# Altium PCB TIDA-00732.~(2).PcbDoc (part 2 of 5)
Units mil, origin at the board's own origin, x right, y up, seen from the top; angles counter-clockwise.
Board outline 8994.78 x 4186 mil, 6 copper layers (Top Layer, GND1, PWR1, PWR2, GND2, Bottom Layer), stack 97.668 mil thick; 693 components, 463 nets, 2087 pads, 616 vias.
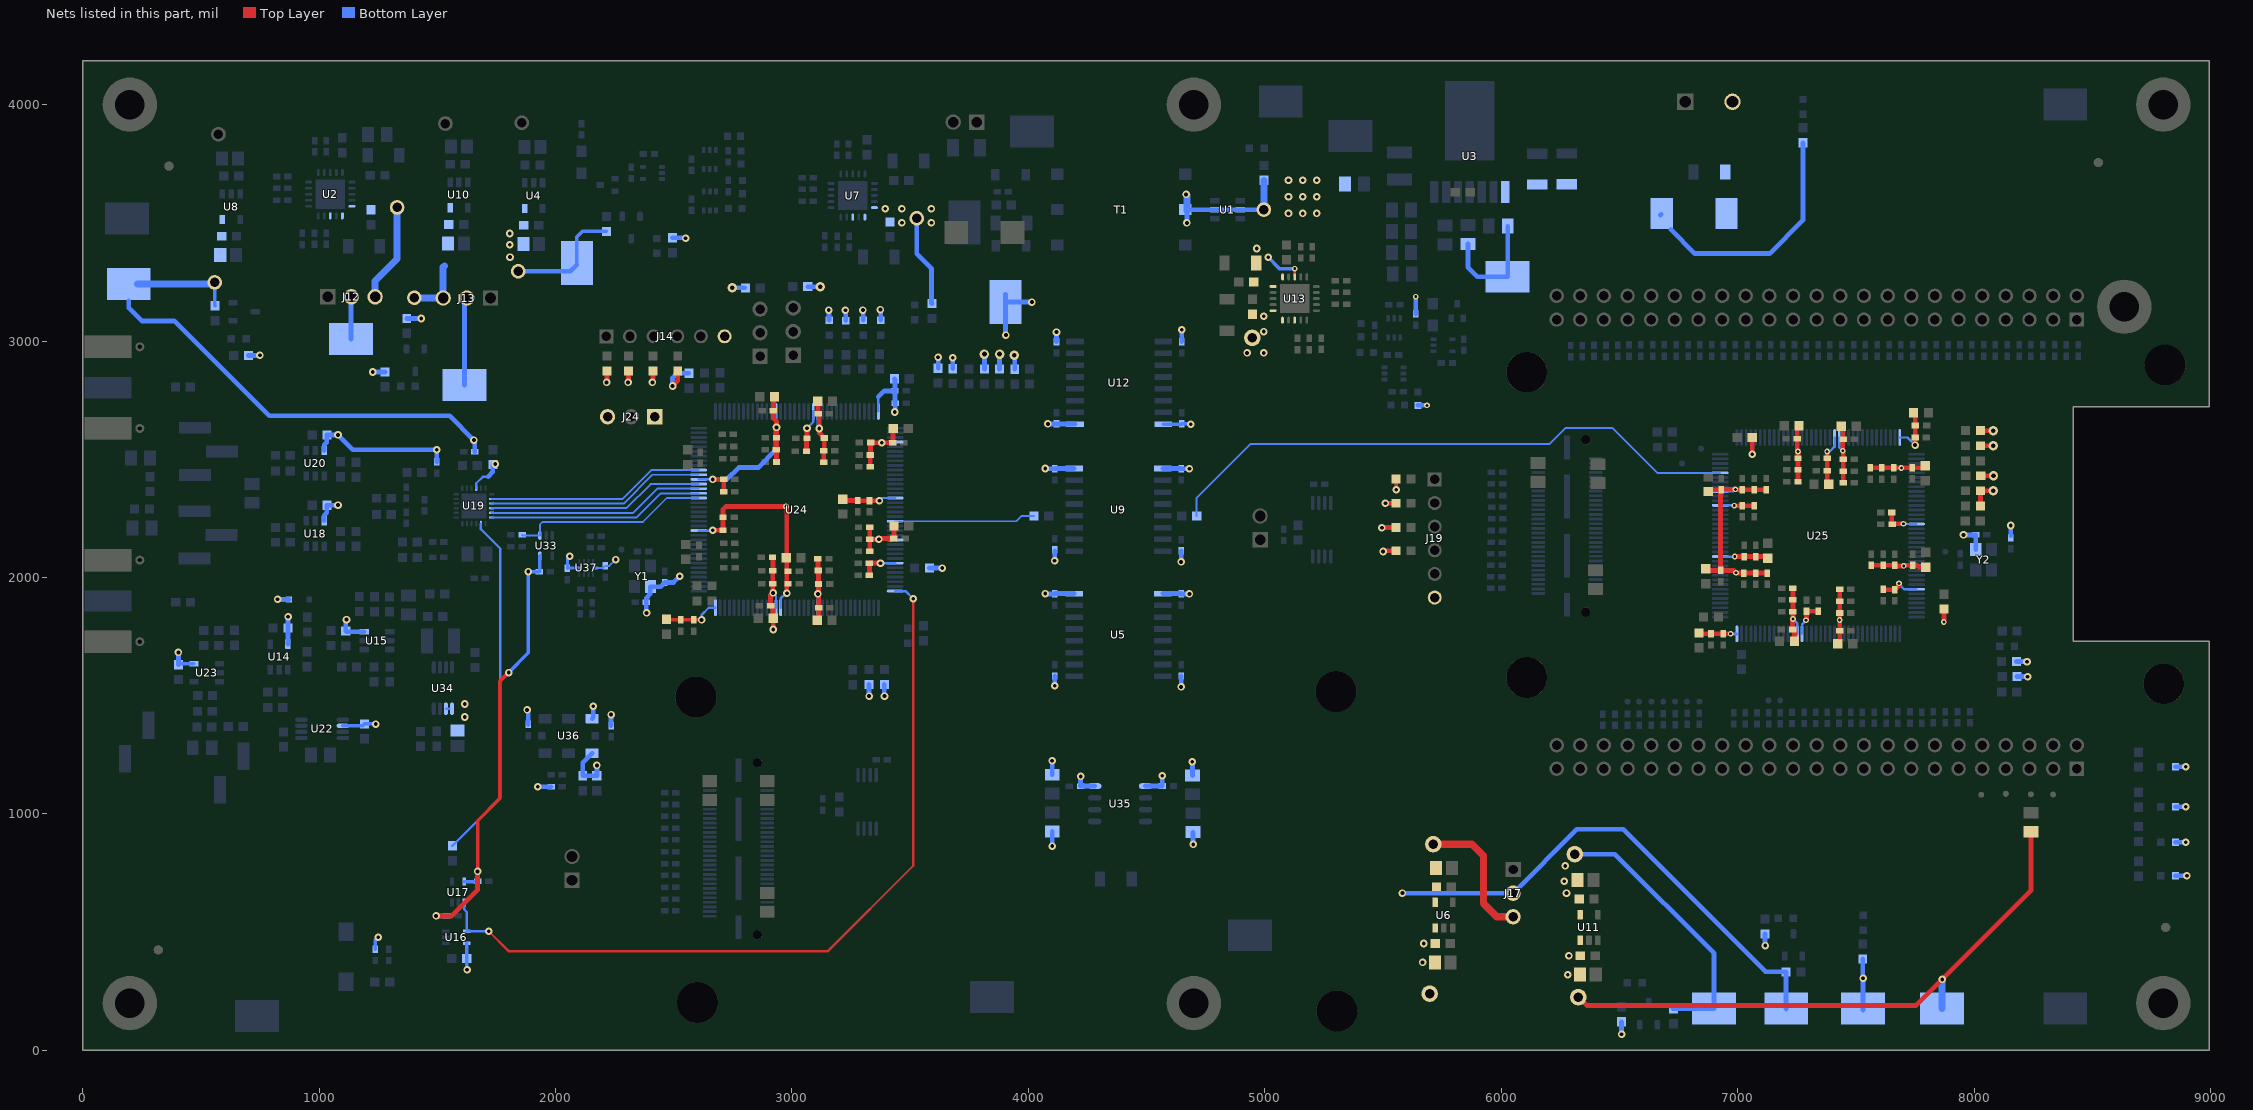
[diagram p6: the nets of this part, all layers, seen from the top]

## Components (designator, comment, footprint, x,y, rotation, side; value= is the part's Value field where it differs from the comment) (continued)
U23 "OPA376AIDBVR" DBV0005A_N 525,1597.02 r180 bottom
U24 "XC3S50AN-5TQG144C" TQ144_N 3021,2287 r270 bottom
U25 "XC3S50AN-5TQG144C" TQ144_N 7341,2177 r270 bottom
U26 "TLV3012AIDCKR" DCK0006A_L 2652,3768 r270 bottom
U27 "SN74LVC1G08DCKR" DCK0005A_L 2410,3711 r180 bottom
U28 "BR24G32FVT-3AGE2" TSOP65P640X120-8N 5240.5,2202 r270 bottom
U29 "TLV3012AIDCKR" DCK0006A_L 2653,3593 r270 bottom
U30 "TLV3012AIDCKR" DCK0006A_L 5546,2863 r180 bottom
U31 "SN74LVC1G08DCKR" DCK0005A_L 5754,2982 r0 bottom
U32 "TLV3012AIDCKR" DCK0006A_L 5547,3056 r90 bottom
U33 "SN74AUP1G80DCK" DCK-5 1960,2135 r0 bottom
U34 "REF6041AIDGK" DGK0008A_N 1523.8,1532.4 r90 bottom
U35 "ISO1541DR" D0008A_N 4388,1043 r180 bottom
U36 "LMK61E2-SIAR" SIA0008B 2055,1330 r90 bottom
U37 "SN65LVDS4RSET" RSE0010A 2129.65,2040.51 r90 bottom
Y1 "ASTMLPE-125.000MHZ-LJ-E-T" TXC_AU 2367.65,2004.51 r0 bottom
Y2 "ASTMLPE-125.000MHZ-LJ-E-T" TXC_AU 8040,2075 r180 bottom
ZZ1 "This Assembly Note is for PCB labels only" AssemblyNoteLabel 400,4620 r0 top
ZZ2 "These assemblies are ESD sensitive, ESD precautions shall be observed." AssemblyNote 397.78,4554.11 r0 top
ZZ3 "These assemblies must be clean and free from flux and all contaminants. Use of no clean flux is not acceptable." AssemblyNote 397.78,4465.56 r0 top
ZZ4 "These assemblies must comply with workmanship standards IPC-A-610 Class 2, unless otherwise specified." AssemblyNote 397.78,4377 r0 top

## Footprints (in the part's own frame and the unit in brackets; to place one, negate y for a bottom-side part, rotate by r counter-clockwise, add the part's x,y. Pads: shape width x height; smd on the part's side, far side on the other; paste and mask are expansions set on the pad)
0402 [mm] "0402 from SM-752 data"
  rect 0.8x0.6 smd: 1(-0.6,0) 2(0.6,0)
  silkscreen extent -1.22,-0.52 1.22,0.52, body extent -0.55,-0.3 0.55,0.3, height 0.6
0603#1 [mm] "0603 from SM-752 data"
  rect 1x0.95 smd: 1(-0.8,0) 2(0.8,0)
  silkscreen extent -1.52,-0.69 1.52,0.69, body extent -0.87,-0.47 0.87,0.47, height 1
0603#2 [mm] "0603 from SM-752 data"
  rect 1x0.95 smd: 1(0.8,0) 2(-0.8,0)
  silkscreen extent -1.52,-0.69 1.52,0.69, body extent -0.87,-0.47 0.87,0.47, height 1
0603_120 [mm] "0603_120"
  rect 1x1 smd: 1(-0.8,0) 2(0.8,0)
  silkscreen extent -0.1,-0.58 0.1,0.58, body extent -0.87,-0.48 0.87,0.48, height 1.2
0603_HV [mil] "Ernesto recommended land pattern.  26 mil between pads."
  rect 30x30 smd: 1(-28,0) 2(28,0)
  silkscreen extent -52,-24 52,24, body extent -34,-19 34,19, height 39
0805 [mm] "0805 from SM-752 data"
  rect 1.3x1.5 smd: 1(-0.85,0) 2(0.85,0)
  silkscreen extent -1.72,-0.97 1.72,0.97, body extent -1.1,-0.72 1.1,0.72, height 1.45
0805_HV [mil] "0805 with 30mil clearance between pads"
  rect 50x63 smd: 1(-40,0) 2(40,0)
  silkscreen extent -74,-40 74,40, body extent -43,-29 43,29, height 57
1206 [mm] "1206 from SM-752 data"
  rect 1.3x1.85 smd: 1(-1.45,0) 2(1.45,0)
  silkscreen extent -2.4,-1.21 2.4,1.21, body extent -1.7,-0.9 1.7,0.9, height 1.35
1206_190 [mm] "1206_190"
  rect 1.1x1.6 smd: 1(-1.7,0) 2(1.7,0)
  silkscreen extent -0.9,-1 0.9,1, body extent -1.75,-0.95 1.75,0.95, height 1.9
1210 [mm] "1210 from SM-752 data"
  rect 1.3x2.7 smd: 1(-1.45,0) 2(1.45,0)
  silkscreen extent -2.32,-1.57 2.32,1.57, body extent -1.7,-1.35 1.7,1.35, height 1.35
1210_280 [mm] "SMD, 2-Leads, Body 3.6x2.8mm, Height 2.8mm"
  rect 1.1x2.2 smd: 1(-1.65,0) 2(1.65,0)
  silkscreen extent -0.84,-1.4 0.84,1.4, body extent -1.8,-1.4 1.8,1.4, height 2.8
7343-43 [mm] "Medium density IPC based on Kemet T495 series"
  rect 2.55x2.45 smd: 1(-3.025,0) 2(3.025,0)
  silkscreen extent -4.56,-2.3 3.8,2.3, body extent -3.8,-2.3 3.8,2.3, height 4.3
APT2012_Green [mm] "SMD, 2-Leads, Body 2x1.25mm"
  rect 1.25x1.1 smd: 1(-1.175,0) 2(1.175,0)
  silkscreen extent -1.5,-1 2.4,1, body extent -1,-0.62 1,0.63, height 0.76
AssemblyNote [mil] "Assembly Note"
AssemblyNoteLabel [mil] "Assembly Note for PCB Labels"
B_F_PMSSS4400025PH [mil] "MACHINE SCREW PAN PHILLIPS 4-40"
  round 230 hole 125: 1(0,0)
  body extent -110,-109 109,110, height 79
CONN_ED120-2DS [mm] "ONSHORE"
  rect 1.75x1.75 hole 1.25: 1(0,-2.54)
  round 1.75 hole 1.25: 2(0,2.54)
  silkscreen extent -5,-5.6 4,5.12, body extent -5,-5.6 4.15,5.12, height 13.1
D0008A_N [mm] "SOIC, 8-Leads, Body 4.9x3.9mm, Pitch 1.27mm, IPC Medium Density"
  oval 1.45x0.6 smd: 1(-2.725,1.905) 2(-2.725,0.635) 3(-2.725,-0.635) 4(-2.725,-1.905) 5(2.725,-1.905) 6(2.725,-0.635) 7(2.725,0.635) 8(2.725,1.905)
  silkscreen extent -3.3,-2.5 0.9,2.5, body extent -3,-2.45 3,2.45, height 1.63
DBV0005A_N [mm] "SOT23, 5-Leads, Body 2.9x1.6mm, Pitch 0.95mm, Lead Span 2.8mm, IPC Medium Density"
  rrect17% 1x0.6 smd: 1(-1.375,0.95) 2(-1.375,0) 3(-1.375,-0.95) 4(1.375,-0.95) 5(1.375,0.95)
  silkscreen extent -1.63,-1.55 0.38,1.55, body extent -1.42,-1.46 1.42,1.46, height 1.09
DBV0006A_N [mm] "SOT23, 6-Leads, Body 2.9x1.6mm, Pitch 0.95mm, Lead Span 2.8mm, IPC Medium Density"
  rrect17% 1x0.6 smd: 1(-1.375,0.95) 2(-1.375,0) 3(-1.375,-0.95) 4(1.375,-0.95) 5(1.375,0) 6(1.375,0.95)
  silkscreen extent -1.68,-1.55 0.5,1.55, body extent -1.42,-1.46 1.42,1.46, height 1.12
DCK0005A_L [mm] "SOT353, 5-Leads, Body 2x1.3mm, Pitch 0.65mm, Lead Span 2.1mm, IPC High Density"
  rrect25% 0.65x0.4 smd: 1(-1.025,0.65) 2(-1.025,0) 3(-1.025,-0.65) 4(1.025,-0.65) 5(1.025,0.65)
  silkscreen extent -1.27,-1.09 0.56,1.09, body extent -1.14,-1 1.14,1, height 0.95
DCK0005A_N [mm] "SOT353, 5-Leads, Body 2x1.3mm, Pitch 0.65mm, Lead Span 2.1mm, IPC Medium Density"
  rrect25% 0.85x0.4 smd: 1(-1.125,0.65) 2(-1.125,0) 3(-1.125,-0.65) 4(1.125,-0.65) 5(1.125,0.65)
  silkscreen extent -1.48,-1.02 0.55,1.1, body extent -1.14,-1 1.14,1, height 0.95
DCK0006A_L [mm] "SOT23, 6-Leads, Body 2x1.3mm, Pitch 0.65mm, Lead Span 2.1mm, IPC High Density"
  rrect25% 0.65x0.4 smd: 1(-1.025,0.65) 2(-1.025,0) 3(-1.025,-0.65) 4(1.025,-0.65) 5(1.025,0) 6(1.025,0.65)
  silkscreen extent -1.3,-1.07 0.55,1.1, body extent -1.14,-1 1.14,1, height 0.95
DCK-5 [mil]
  oval 15x38 smd: 1(-25.9,-43.4) 2(0.1,-43.4) 3(26.1,-43.4) 4(26.1,43.6) 5(-25.9,43.6)
DGK0008A_N [mm] "TSOP, 8-Leads, Body 3x3mm, Pitch 0.65mm, IPC Medium Density"
  oval 1.35x0.45 smd: 1(-2.225,0.975) 2(-2.225,0.325) 3(-2.225,-0.325) 4(-2.225,-0.975) 5(2.225,-0.975) 6(2.225,-0.325) 7(2.225,0.325) 8(2.225,0.975)
  silkscreen extent -2.75,-1.55 0.95,1.55, body extent -2.45,-1.5 2.45,1.5, height 0.96
DW0016B_N [mm] "SOIC, 16-Leads, Body 10.5x7.6mm, Pitch 1.27mm, IPC Medium Density"
  rrect17% 1.9x0.6 smd: 1(-4.75,4.445) 2(-4.75,3.175) 3(-4.75,1.905) 4(-4.75,0.635) 5(-4.75,-0.635) 6(-4.75,-1.905) 7(-4.75,-3.175) 8(-4.75,-4.445) 9(4.75,-4.445) 10(4.75,-3.175) 11(4.75,-1.905) 12(4.75,-0.635) 13(4.75,0.635) 14(4.75,1.905) 15(4.75,3.175) 16(4.75,4.445)
  silkscreen extent -5.6,-5.25 3.4,5.25, body extent -5.17,-5.15 5.17,5.15, height 2.59
Fiducial10-20 [mm]
  round 1 smd mask+0.5: 1(0,0)
  Top Layer keep-out circle w1.178: c0,0 r0.5
JOHNSON_142-0701-801 [mil] "Johnson Components recommended land pattern"
  rect 90x200 smd: 1(0,0)
  round 38 hole 18: 2(-172.5,-135) 3(172.5,-135)
  rect 95x200 smd: 2(-172.5,0) 3(172.5,0)
  rect 95x200 smd far side: 4(-172.5,0) 5(172.5,0)
  Top Layer lines w18: 172.5,0 172.5,-135 ; -172.5,0 -172.5,-135
  Bottom Layer lines w18: 172.5,0 172.5,-135 ; -172.5,0 -172.5,-135
  silkscreen extent -235,-170 235,100, body extent -190,-92 190,480, height 165
Keystone_1902C [mil] "Hex Standoff, 4-40 threaded, nylon"
  round 1 on Mech3: 0(0,0)
  body extent -145,-126 146,126, height 501
Label_650x200 [mil] "Thermal Transfer Label"
  round 1 on Mech14: 0(0,0)
  silkscreen extent -325,-100 325,100, body extent -326,-101 326,101, height 1
Molex_87898-0204 [mm] "Header, 2.54 mm, 2x1, R/A, SMT"
  rect 1.27x2.96 smd: 1(-1.27,1.8) 2(1.27,-1.8)
  silkscreen extent -2.54,-1.27 2.54,1.27, body extent -2.54,-2.4 2.54,2.4, height 9.65
RGE0024H [mm] "QFN, 24-Leads, Body 4x4mm, Pitch 0.5mm, Thermal Pad 2.7x2.7mm, TI Recommended"
  oval 0.6x0.24 smd: 1(-1.9,1.25) 2(-1.9,0.75) 3(-1.9,0.25) 4(-1.9,-0.25) 5(-1.9,-0.75) 6(-1.9,-1.25) 13(1.9,-1.25) 14(1.9,-0.75) 15(1.9,-0.25) 16(1.9,0.25) 17(1.9,0.75) 18(1.9,1.25)
  oval 0.24x0.6 smd: 7(-1.25,-1.9) 8(-0.75,-1.9) 9(-0.25,-1.9) 10(0.25,-1.9) 11(0.75,-1.9) 12(1.25,-1.9) 19(1.25,1.9) 20(0.75,1.9) 21(0.25,1.9) 22(-0.25,1.9) 23(-0.75,1.9) 24(-1.25,1.9)
  rect 2.7x2.7 smd paste-1.35: 25(0,0)
  silkscreen extent -2.22,-2.22 2.22,2.22, body extent -2.07,-2.07 2.07,2.07, height 1.01
RGW0020A [mm] "QFN, 20-Leads, Body 5x5mm, Pitch 0.65mm, Thermal Pad 3.15x3.15mm, TI Recommended"
  oval 0.75x0.3 smd: 1(-2.325,1.3) 2(-2.325,0.65) 3(-2.325,0) 4(-2.325,-0.65) 5(-2.325,-1.3) 11(2.325,-1.3) 12(2.325,-0.65) 13(2.325,0) 14(2.325,0.65) 15(2.325,1.3)
  oval 0.3x0.75 smd: 6(-1.3,-2.325) 7(-0.65,-2.325) 8(0,-2.325) 9(0.65,-2.325) 10(1.3,-2.325) 16(1.3,2.325) 17(0.65,2.325) 18(0,2.325) 19(-0.65,2.325) 20(-1.3,2.325)
  rect 3.15x3.15 smd paste-1.575: 21(0,0)
  silkscreen extent -2.73,-2.73 2.73,2.73, body extent -2.58,-2.57 2.57,2.58, height 1.01
RSE0010A [mm] "QFN, 10-Leads, Body 1.5x2mm, Pitch 0.5mm, TI Recommended"
  rect 0.55x0.2 smd: 1(-0.675,0.75) 2(-0.675,0.25) 3(-0.675,-0.25) 4(-0.675,-0.75) 6(0.675,-0.75) 7(0.675,-0.25) 8(0.675,0.25) 9(0.675,0.75)
  rect 0.3x0.6 smd: 5(0,-0.9) 10(0,0.9)
  silkscreen extent -1.07,-1.17 0.77,1.18, body extent -0.77,-1.02 0.78,1.03, height 0.61
Samtec_HTSW-103-07-G-S [mm] "Samtec 100mil, 1x3, 230 mil above insulator"
  rect 1.65x1.65 hole 1.016 mask+0: 1(-2.54,0)
  round 1.65 hole 1.016 mask+0: 2(0,0) 3(2.54,0)
  silkscreen extent -4.57,-1.27 3.81,1.27, body extent -3.81,-1.27 3.81,1.27, height 8.38
Samtec_QTH-030-01-x-D-A [mil] "Header (Shrouded), 19.7mil, 30x2, SMT"
  rect 12x57 smd: 1(-285.7,121.5) 2(-285.7,-121.5) 3(-266,121.5) 4(-266,-121.5) 5(-246.3,121.5) 6(-246.3,-121.5) 7(-226.6,121.5) 8(-226.6,-121.5) 9(-206.9,121.5) 10(-206.9,-121.5) 11(-187.2,121.5) 12(-187.2,-121.5) 13(-167.5,121.5) 14(-167.5,-121.5) 15(-147.8,121.5) 16(-147.8,-121.5) 17(-128.1,121.5) 18(-128.1,-121.5) 19(-108.4,121.5) 20(-108.4,-121.5) 21(-88.7,121.5) 22(-88.7,-121.5) 23(-69,121.5) 24(-69,-121.5) 25(-49.3,121.5) 26(-49.3,-121.5) 27(-29.6,121.5) 28(-29.6,-121.5) 29(-9.9,121.5) 30(-9.9,-121.5) 31(9.8,121.5) 32(9.8,-121.5) 33(29.5,121.5) 34(29.5,-121.5) 35(49.2,121.5) 36(49.2,-121.5) 37(68.9,121.5) 38(68.9,-121.5) 39(88.6,121.5) 40(88.6,-121.5) 41(108.3,121.5) 42(108.3,-121.5) 43(128,121.5) 44(128,-121.5) 45(147.7,121.5) 46(147.7,-121.5) 47(167.4,121.5) 48(167.4,-121.5) 49(187.1,121.5) 50(187.1,-121.5) 51(206.8,121.5) 52(206.8,-121.5) 53(226.5,121.5) 54(226.5,-121.5) 55(246.2,121.5) 56(246.2,-121.5) 57(265.9,121.5) 58(265.9,-121.5) 59(285.6,121.5) 60(285.6,-121.5)
  round 40 hole 40 unplated mask+10: MH1(-364,80) MH2(364,80)
  rect 100x25 smd: MP1(-332.7,0) MP4(332.3,0)
  rect 185x25 smd: MP2(-125.2,0) MP3(124.8,0)
  silkscreen extent -394,-118 394,131, body extent -394,-140 394,140, height 170
Samtec_TSM-103-01-X-SV [mil] "Samtec recommended land pattern"
  rect 50x135 smd: 1(-100,57.5) 2(0,-57.5) 3(100,57.5)
  silkscreen extent -150,-50 150,50, body extent -150,-104 150,104, height 381
Samtec_TSW-123-07-x-D#1 [mm] "Header, 2.54 mm, 23x2, TH"
  rect 1.55x1.55 hole 1.02: 1(-1.27,-27.94)
  round 1.55 hole 1.02: 2(1.27,-27.94) 3(-1.27,-25.4) 4(1.27,-25.4) 5(-1.27,-22.86) 6(1.27,-22.86) 7(-1.27,-20.32) 8(1.27,-20.32) 9(-1.27,-17.78) 10(1.27,-17.78) 11(-1.27,-15.24) 12(1.27,-15.24) 13(-1.27,-12.7) 14(1.27,-12.7) 15(-1.27,-10.16) 16(1.27,-10.16) 17(-1.27,-7.62) 18(1.27,-7.62) 19(-1.27,-5.08) 20(1.27,-5.08) 21(-1.27,-2.54) 22(1.27,-2.54) 23(-1.27,0) 24(1.27,0) 25(-1.27,2.54) 26(1.27,2.54) 27(-1.27,5.08) 28(1.27,5.08) 29(-1.27,7.62) 30(1.27,7.62) 31(-1.27,10.16) 32(1.27,10.16) 33(-1.27,12.7) 34(1.27,12.7) 35(-1.27,15.24) 36(1.27,15.24) 37(-1.27,17.78) 38(1.27,17.78) 39(-1.27,20.32) 40(1.27,20.32) 41(-1.27,22.86) 42(1.27,22.86) 43(-1.27,25.4) 44(1.27,25.4) 45(-1.27,27.94) 46(1.27,27.94)
  silkscreen extent -2.54,-29.76 2.54,29.21, body extent -2.54,-29.21 2.54,29.21, height 2.54
Samtec_TSW-123-07-x-D#2 [mm] "Header, 2.54 mm, 23x2, TH"
  rect 1.55x1.55 hole 1.02: 1(-1.27,0.254)
  round 1.55 hole 1.02: 2(1.27,0.254) 3(-1.27,2.794) 4(1.27,2.794) 5(-1.27,5.334) 6(1.27,5.334) 7(-1.27,7.874) 8(1.27,7.874) 9(-1.27,10.414) 10(1.27,10.414) 11(-1.27,12.954) 12(1.27,12.954) 13(-1.27,15.494) 14(1.27,15.494) 15(-1.27,18.034) 16(1.27,18.034) 17(-1.27,20.574) 18(1.27,20.574) 19(-1.27,23.114) 20(1.27,23.114) 21(-1.27,25.654) 22(1.27,25.654) 23(-1.27,28.194) 24(1.27,28.194) 25(-1.27,30.734) 26(1.27,30.734) 27(-1.27,33.274) 28(1.27,33.274) 29(-1.27,35.814) 30(1.27,35.814) 31(-1.27,38.354) 32(1.27,38.354) 33(-1.27,40.894) 34(1.27,40.894) 35(-1.27,43.434) 36(1.27,43.434) 37(-1.27,45.974) 38(1.27,45.974) 39(-1.27,48.514) 40(1.27,48.514) 41(-1.27,51.054) 42(1.27,51.054) 43(-1.27,53.594) 44(1.27,53.594) 45(-1.27,56.134) 46(1.27,56.134)
  silkscreen extent -2.54,-1.57 2.54,57.4, body extent -2.54,-1.02 2.54,57.4, height 2.54
SIA0008B [mm] "SIP 8-Leads, Body 5x7mm"
  rrect17% 1x0.6 on Bottom Paste: 1(-1.85,2.14) 1(-1.85,2.94) 2(-1.85,-0.4) 2(-1.85,0.4) 3(-1.85,-2.94) 3(-1.85,-2.14) 4(1.85,-2.94) 4(1.85,-2.14) 5(1.85,-0.4) 5(1.85,0.4) 6(1.85,2.14) 6(1.85,2.94)
  rrect10% 1x1.4 smd paste-0.5: 1(-1.85,2.54) 2(-1.85,0) 3(-1.85,-2.54) 4(1.85,-2.54) 5(1.85,0) 6(1.85,2.54)
  rrect12% 0.8x0.8 smd: 7(0,2.865) 8(0,-2.865)
  silkscreen extent -2.64,-3.63 2.64,3.63, body extent -2.56,-3.56 2.56,3.56, height 1.13
SMC [mm] "DO-214-AB/SMC; 2 C-Bend Leads; Body 7.9 x 5.9 mm, inc. leads (LxW)"
  rect 2.4x3.3 smd: 1(3.475,0) 2(-3.475,0)
  silkscreen extent -5.43,-2.05 5.07,2.05
SOD-123 [mm] "On Semi recommended land pattern"
  rect 0.915x1.22 smd: 1(-1.637,0) 2(1.637,0)
  silkscreen extent -2.74,-1.17 2.03,1.17, body extent -1.93,-0.9 1.93,0.9, height 1.35
sod-323 [mm] "NXP recommended land pattern"
  rect 0.6x0.6 smd paste-0.05: 1(-1.1,0) 2(1.1,0)
  silkscreen extent -2.06,-0.86 1.53,0.86, body extent -1.3,-0.67 1.3,0.68, height 1.1
SOT-23 [mm] "SOT23, 3-Leads, Body 2.9x1.3mm, Pitch 0.95mm, Lead Span 2.5mm, IPC Medium Density"
  rrect50% 1x0.6 smd: 1(-1.2,0.95) 2(-1.2,-0.95) 3(1.2,0)
  silkscreen extent -1.62,-1.5 0.7,1.5, body extent -1.16,-1.45 1.21,1.45, height 1
SOT-323 [mm] "Zetex recommended land pattern.  March 2007"
  rect 0.8x0.6 smd: 1(-0.8,0.65) 2(-0.8,-0.65) 3(0.8,0)
  silkscreen extent -1.14,-1.22 0.77,1.22, body extent -1.13,-1.13 1.12,1.12, height 1.13
Sullins_PEC06SAAN [mm] "TH, 6-Leads, Body 608x100mil, Pitch 100mil"
  rect 1.5x1.5 hole 1.016: 1(-6.35,0)
  round 1.5 hole 1.016: 2(-3.81,0) 3(-1.27,0) 4(1.27,0) 5(3.81,0) 6(6.35,0)
  silkscreen extent -8.64,-1.27 7.72,1.27, body extent -7.72,-1.27 7.72,1.27, height 8.59
SW_EVQPNF04M [mm] "SMD, 2-Leads, Body 6x4mm"
  rect 2x1.6 smd: 1(-2.7,0) 2(2.7,0)
  silkscreen extent -4.37,-1.75 3,1.75, body extent -3.6,-1.75 3.6,1.75, height 4.3
Testpoint_Keystone_Compact [mil] "Compact SMT test point"
  rect 185x135 smd: 1(0,0)
  silkscreen extent -110,-80 110,80, body extent -75,-56 75,56, height 91
TI_Stacked_Overlay_Small [mil]
  silkscreen extent -418,-98 418,98
TP-040_RND [mil]
  round 70 / inner round 62 / far side round 62 hole 40: 1(0,0)
TP_25MIL-SMT [mil]
  round 25 smd mask-2.5: 1(0,0)
TQ144_N [mm] "Thin QFP, 144-Leads, Body 20x20mm, Pitch 0.5mm, IPC Medium Density"
  oval 1.8x0.3 smd: 1(-10.55,8.75) 2(-10.55,8.25) 3(-10.55,7.75) 4(-10.55,7.25) 5(-10.55,6.75) 6(-10.55,6.25) 7(-10.55,5.75) 8(-10.55,5.25) 9(-10.55,4.75) 10(-10.55,4.25) 11(-10.55,3.75) 12(-10.55,3.25) 13(-10.55,2.75) 14(-10.55,2.25) 15(-10.55,1.75) 16(-10.55,1.25) 17(-10.55,0.75) 18(-10.55,0.25) 19(-10.55,-0.25) 20(-10.55,-0.75) 21(-10.55,-1.25) 22(-10.55,-1.75) 23(-10.55,-2.25) 24(-10.55,-2.75) 25(-10.55,-3.25) 26(-10.55,-3.75) 27(-10.55,-4.25) 28(-10.55,-4.75) 29(-10.55,-5.25) 30(-10.55,-5.75) 31(-10.55,-6.25) 32(-10.55,-6.75) 33(-10.55,-7.25) 34(-10.55,-7.75) 35(-10.55,-8.25) 36(-10.55,-8.75) 73(10.55,-8.75) 74(10.55,-8.25) 75(10.55,-7.75) 76(10.55,-7.25) 77(10.55,-6.75) 78(10.55,-6.25) 79(10.55,-5.75) 80(10.55,-5.25) 81(10.55,-4.75) 82(10.55,-4.25) 83(10.55,-3.75) 84(10.55,-3.25) 85(10.55,-2.75) 86(10.55,-2.25) 87(10.55,-1.75) 88(10.55,-1.25) 89(10.55,-0.75) 90(10.55,-0.25) 91(10.55,0.25) 92(10.55,0.75) 93(10.55,1.25) 94(10.55,1.75) 95(10.55,2.25) 96(10.55,2.75) 97(10.55,3.25) 98(10.55,3.75) 99(10.55,4.25) 100(10.55,4.75) 101(10.55,5.25) 102(10.55,5.75) 103(10.55,6.25) 104(10.55,6.75) 105(10.55,7.25) 106(10.55,7.75) 107(10.55,8.25) 108(10.55,8.75)
  oval 0.3x1.8 smd: 37(-8.75,-10.55) 38(-8.25,-10.55) 39(-7.75,-10.55) 40(-7.25,-10.55) 41(-6.75,-10.55) 42(-6.25,-10.55) 43(-5.75,-10.55) 44(-5.25,-10.55) 45(-4.75,-10.55) 46(-4.25,-10.55) 47(-3.75,-10.55) 48(-3.25,-10.55) 49(-2.75,-10.55) 50(-2.25,-10.55) 51(-1.75,-10.55) 52(-1.25,-10.55) 53(-0.75,-10.55) 54(-0.25,-10.55) 55(0.25,-10.55) 56(0.75,-10.55) 57(1.25,-10.55) 58(1.75,-10.55) 59(2.25,-10.55) 60(2.75,-10.55) 61(3.25,-10.55) 62(3.75,-10.55) 63(4.25,-10.55) 64(4.75,-10.55) 65(5.25,-10.55) 66(5.75,-10.55) 67(6.25,-10.55) 68(6.75,-10.55) 69(7.25,-10.55) 70(7.75,-10.55) 71(8.25,-10.55) 72(8.75,-10.55) 109(8.75,10.55) 110(8.25,10.55) 111(7.75,10.55) 112(7.25,10.55) 113(6.75,10.55) 114(6.25,10.55) 115(5.75,10.55) 116(5.25,10.55) 117(4.75,10.55) 118(4.25,10.55) 119(3.75,10.55) 120(3.25,10.55) 121(2.75,10.55) 122(2.25,10.55) 123(1.75,10.55) 124(1.25,10.55) 125(0.75,10.55) 126(0.25,10.55) 127(-0.25,10.55) 128(-0.75,10.55) 129(-1.25,10.55) 130(-1.75,10.55) 131(-2.25,10.55) 132(-2.75,10.55) 133(-3.25,10.55) 134(-3.75,10.55) 135(-4.25,10.55) 136(-4.75,10.55) 137(-5.25,10.55) 138(-5.75,10.55) 139(-6.25,10.55) 140(-6.75,10.55) 141(-7.25,10.55) 142(-7.75,10.55) 143(-8.25,10.55) 144(-8.75,10.55)
  silkscreen extent -10.67,-9.25 9.25,9.57, body extent -10,-10 10,10, height 1.6
TSOP65P640X120-8N [mm] "TSOP, 8-Leads, Body 3.1x4.5mm (max), Pitch 0.65mm, IPC Medium Density"
  oval 1.55x0.35 smd mask+0.08: 1(-2.875,0.975) 2(-2.875,0.325) 3(-2.875,-0.325) 4(-2.875,-0.975) 5(2.875,-0.975) 6(2.875,-0.325) 7(2.875,0.325) 8(2.875,0.975)
  silkscreen extent -1.7,-1.55 1.7,1.55, body extent -2.25,-1.55 2.25,1.55, height 1.21
TXC_AU [mm] "SMD, 4-Leads, Body 3.2x2.5mm"
  rect 1.2x1.4 smd: 1(-0.85,1.1) 2(-0.85,-1.1) 3(0.85,-1.1) 4(0.85,1.1)
  silkscreen extent -2.05,-0.1 1.3,1.33, body extent -1.3,-1.65 1.3,1.65, height 1.11
TZA07A_V [mm] "D2-PAK, 8-Leads, Body 9.9x10.2mm, Pitch 1.27mm, Lead Span 13.8mm, NSC Recommended"
  rect 2.41x0.89 smd: 1(-5.35,3.81) 2(-5.35,2.54) 3(-5.35,1.27) 4(-5.35,0) 5(-5.35,-1.27) 6(-5.35,-2.54) 7(-5.35,-3.81)
  rect 8.54x5.35 smd: 8(2.28,0)
  silkscreen extent -5.47,-5.15 -2.7,5.15, body extent -2.55,-5.2 7.55,5.2, height 4.67
WL-SMCW_RED [mm] "WURTH"
  rect 0.8x0.8 smd: 1(-0.8,0) 2(0.8,0)
  silkscreen extent -1.9,-0.8 1.2,0.8, body extent -0.85,-0.45 0.85,0.45, height 0.8
Wurth_750315240 [mm] "SMD, 6-Leads, Body 10.41x12.32mm"
  rect 1.335x1.215 smd: 1(-6.87,3.81) 2(-6.87,0) 3(-6.87,-3.81) 4(6.87,-3.81) 5(6.87,0) 6(6.87,3.81)
  silkscreen extent -5.21,-6.16 5.21,6.5, body extent -7.43,-6.16 7.43,6.16, height 11.06
WURTH_61300211121 [mm] "Header, 2.54mm, 2x1, TH"
  rect 1.65x1.65 hole 1.15: 1(-1.27,0)
  round 1.65 hole 1.15: 2(1.27,0)
  silkscreen extent -2.54,-1.27 2.54,1.6, body extent -2.54,-1.27 2.54,1.27, height 8.54
WURTH_61300311121 [mm] "Header, 2.54mm, 3x1, TH"
  rect 1.65x1.65 hole 1.15: 1(-2.54,0)
  round 1.65 hole 1.15: 2(0,0) 3(2.54,0)
  silkscreen extent -3.81,-1.27 3.81,1.6, body extent -3.81,-1.27 3.81,1.27, height 8.54
Wurth_WA-SMSI [mm] "ROUND STANDOFF M3 STEEL 5MM"
  round 4.4 hole 4.4 unplated mask+0.254: ""(0,0)
  Top Layer region: -3.7,0 -3.334,-1.605 -2.307,-2.893 -0.823,-3.607 0.823,-3.607 2.307,-2.893 3.334,-1.605 3.7,0 3.7,0 2.454,0 2.211,-1.065 1.53,-1.919 0.546,-2.392 -0.546,-2.392 -1.53,-1.919 -2.211,-1.065 -2.454,0 -2.454,0
  Top Layer region: -3.7,0 -3.334,1.605 -2.307,2.893 -0.823,3.607 0.823,3.607 2.307,2.893 3.334,1.605 3.7,0 3.7,0 2.454,0 2.211,1.065 1.53,1.919 0.546,2.392 -0.546,2.392 -1.53,1.919 -2.211,1.065 -2.454,0 -2.454,0
  silkscreen extent -4.1,-4.1 4.1,4.1, body extent -2.99,-2.98 2.99,3, height 5

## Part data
C1: "CAP, CERM, 47 µF, 10 V, +/- 10%, X7R, 1210"
C2 C10 C24 C48 C53 C56 C62 C63 C65 C70 C72 C74 C79 C80: "CAP, CERM, 1 µF, 25 V, +/- 10%, X7R, 0603"
C3 C11 C12 C25 C26 C43 C44 C51 C59 C75 C78 C85 C86 C128 C133 C150 C155 C192 C220 C222 C223 C224 C225 C226 C229 C230 C231: "CAP, CERM, 0.1 µF, 16 V, +/- 10%, X7R, 0402"
C4 C64 C69 C76 C81 C82 C83 C84 C87 C89 C90: "CAP, CERM, 10 µF, 10 V, +/- 10%, X7R, 0805"
C5 C9 C17 C23 C45 C47: "CAP, CERM, 47 µF, 25 V, +/- 20%, X5R, 1206_190"
C6 C8: "CAP, CERM, 10 µF, 25 V, +/- 20%, X7R, 1206_190"
C7 C18 C46 C67 C73: "CAP, CERM, 1000 pF, 50 V, +/- 1%, C0G/NP0, 0603"
C13 C19 C27 C31 C35: "CAP, CERM, 1uF, 50V, +/-10%, X7R, 0805"
C14 C16 C20 C22 C28 C30 C32 C34 C36 C38: "CAP, CERM, 0.1uF, 50V, +/-10%, X7R, 0603"
C15 C21 C29 C33 C37: "CAP, CERM, 10uF, 16V, +/-20%, X5R, 0805"
C39 C40: "CAP, CERM, 10 µF, 50 V, +/- 10%, X7R, 1210"
C41: "CAP, CERM, 0.01uF, 50V, +/-5%, X7R, 0603"
C42: "CAP, CERM, 0.022uF, 50V, +/-10%, X7R, 0805"
C49 C96 C97 C106 C107 C120 C121 C122 C123 C142 C143 C144 C145 C160 C161 C170 C171 C184 C185 C186 C187 C206 C207 C208 C209 C219 C228 C233: "CAP, CERM, 10 µF, 10 V, +/- 10%, X7T, 0603"
C50: "CAP, CERM, 0.1 µF, 16 V, +/- 5%, X7R, 0603"
C52: "CAP, CERM, 0.22 µF, 16 V, +/- 5%, X7R, 0805"
C54 C55 C60 C77 C232: "CAP, CERM, 0.1 µF, 25 V, +/- 5%, X7R, 0603"
C57 C58: "CAP, CERM, 22 µF, 6.3 V, +/- 20%, X5R, 0603"
C61: "CAP, CERM, 10 pF, 50 V, +/- 1%, C0G/NP0, 0603"
C66 C71 C214 C221 C227: "CAP, CERM, 0.01 µF, 50 V, +/- 10%, X7R, 0402"
C68: "CAP, CERM, 0.01 µF, 100 V, +/- 1%, C0G/NP0, 0805"
C88: "CAP, CERM, 10uF, 10V, +/-10%, X7R, 0805"
C91: "CAP, CERM, 22uF, 10V, +/-20%, X5R, 1210"
C92 C93 C94 C95 C102 C103 C104 C105 C112 C113 C114 C115 C116 C117 C118 C119 C134 C135 C136 C137 C138 C139 C140 C141 C156 C157 C158 C159 C166 C167 C168 C169 C176 C177 C178 C179 C180 C181 C182 C183 C198 C199 C200 C201 C202 C203 C204 C205: "CAP, CERM, 1000 pF, 50 V, +/- 20%, X7R, 0402"
C98 C99 C100 C101 C108 C109 C110 C111 C124 C125 C126 C127 C129 C130 C131 C132 C146 C147 C148 C149 C151 C152 C153 C154 C162 C163 C164 C165 C172 C173 C174 C175 C188 C189 C190 C191 C193 C194 C195 C196 C210 C211 C212 C213 C215 C216 C217 C218: "CAP, CERM, 0.047 µF, 10 V, +/- 10%, X5R, 0402"
C197: "CAP, CERM, 1uF, 10V, +/-10%, X7R, 0603"
C234 C235: "CAP, CERM, 0.1 µF, 25 V, +/- 10%, X5R, 0402"
C236: "CAP, CERM, 1000 pF, 2000 V, +/- 10%, X7R, 1206_190"
C237: "CAP, TA, 100 µF, 20 V, +/- 10%, 0.5 ohm, SMD"
D1 D3: "Diode, Schottky, 20 V, 0.5 A, SOD-123"
D2: "Diode, Schottky, 200V, 4A, SMC"
D4: "Diode, Schottky, 40 V, 0.5 A, SOD-323"
D5 D6 D7 D8 D9 D10 D11 D12 D13 D14 D15 D16 D17 D18 D19 D22 D23 D24 D25: "LED, Red, SMD"
D20 D21: "LED, Green, SMD"
FID1 FID2 FID3 FID4 FID5 FID6 FID7 FID8: "Fiducial mark.  There is nothing to buy or mount."
H1 H2 H3 H4 H17 H18 H21: "MACHINE SCREW PAN PHILLIPS 4-40"
H5 H6 H7 H8 H13 H14 H15 H16: "ROUND STANDOFF M3 STEEL 11MM"
H9 H10 H11 H12 H19 H20 H30: "Standoff, Hex, 0.5\"L #4-40 Nylon"
J1 J2: "Header, 2.54 mm, 23x2, Gold, TH"
J3 J18: library part QTH-030-01-L-D-A, "Header(Shrouded), 19.7mil, 30x2, Gold, SMT"
J4 J21 J25: "Header, 2.54 mm, 2x1, Gold, TH"
J5: "TERMINAL BLOCK 5.08MM VERT 2POS, TH"
J6 J9: "Header, 100mil, 3x1, Gold, SMT"
J7 J8: "Connector, End launch SMA, 50 ohm, SMT"
J10 J11: "Header, 2.54 mm, 2x1, Gold, R/A, SMT"
J12 J13: "Header, 2.54 mm, 3x1, Gold, TH"
J14 J19: "Header, 100mil, 6x1, Tin, TH"
J16 J17 J22 J24: "Header, 100mil, 3x1, Gold, TH"
L1: "Ferrite Bead, 600 ohm @ 100 MHz, 0.5 A, 0805"
L2: "Ferrite Bead, 600 ohm @ 100MHz, 2A, 0805"
LBL1: library part THT-14-423-10, "Thermal Transfer Printable Labels, 0.650\" W x 0.200\" H - 10,000 per roll"
Logo1: library part TI_Logo, "Texas Instrument Corporate Signature"
Q1 Q2 Q3 Q4 Q5: library part "CMPT3904 LEAD FREE, Central Semiconductor", "Transistor, NPN, 40 V, 0.2 A, SOT-23"
Q6 Q7: "MOSFET, N-CH, 30 V, 0.18 A, SOT-323"
R1 R2 R3 R4 R5 R6 R7 R8 R9 R10 R11 R12 R13 R14 R15 R16 R17 R18 R19 R20 R21 R22 R23 R24 R25 R26 R27 R28 R29 R30 R31 R32 R33 R34 R35 R36 R37 R38 R39 R40 R41 R42 R43 R44 R123 R124 R125 R126 R127 R128 R129 R130 R131 R132 R133 R134 R135 R136 R137 R138 R139 R140 R141 R142 R143 R144 R145 R146 R147 R148 R149 R150 R151 R152: "RES, 10.0, 1%, 0.063 W, 0402"
R45 R53 R54 R55 R56 R57 R58 R59 R60 R64 R65 R66 R67 R68 R69 R70 R71 R77 R78 R79 R80 R81 R82 R83 R84 R102 R160 R162 R163 R164 R166 R169 R170 R171 R172 R173 R175 R186 R189 R190 R193 R195 R199 R200 R208 R210 R212 R213 R215 R261: "RES, 0, 5%, 0.063 W, 0402"
R46 R47: "RES, 0.22 ohm, 1%, 0.1W, 0603"
R48 R49 R97 R103: "RES, 0, 5%, 0.1 W, 0603"
R50 R204 R205 R206: "RES, 1.5 k, 5%, 0.125 W, 0805"
R51: "RES, 0, 5%, 0.25 W, 1206"
R52 R63 R76: "RES, 0.1, 1%, 0.1 W, 0603"
R61 R62 R72 R73 R74 R75 R90 R93 R100 R247 R250 R254 R257: "RES, 10.0 k, 1%, 0.1 W, 0402"
R85 R91 R98 R99 R104 R105: "RES, 1.00 k, 0.1%, 0.1 W, 0603"
R86: "RES, 2.49 k, 0.1%, 0.1 W, 0603"
R87: "RES, 100 k, 1%, 0.063 W, 0402"
R88: "RES, 4.99 k, 0.1%, 0.1 W, 0603"
R89: "RES, 4.75, 1%, 0.1 W, 0603"
R92 R110: "RES, 499, 0.1%, 0.1 W, 0603"
R94: "RES, 30.0 k, 0.1%, 0.1 W, 0603"
R95 R101: "RES, 2.21, 1%, 0.1 W, 0603"
R96 R108 R115 R116 R117 R118 R192 R194 R197 R198: "RES, 100, 0.1%, 0.1 W, 0603"
R106 R111 R114: "RES, 20.0 k, 0.1%, 0.1 W, 0603"
R107 R119 R120 R121 R122 R153 R154 R155 R156 R157 R158 R159 R165 R168 R174 R176 R177 R178 R181 R182 R183 R184 R185 R187 R188 R191 R196 R201 R202 R203 R211 R214 R216 R217 R218 R243: "RES, 1.00 k, 1%, 0.1 W, 0603"
R109: "RES, 280 k, 0.1%, 0.125 W, 0805"
R112 R249 R252 R256 R258: "RES, 10.0 k, 0.1%, 0.1 W, 0603"
R113: "RES, 0.22, 1%, 0.1 W, 0603"
R161 R167 R179 R180 R269 R273: "RES, 33, 5%, 0.063 W, 0402"
R207 R260: "RES, 33.0, 1%, 0.1 W, 0603"
R209 R227 R228 R229 R230 R234 R237 R238 R241 R242 R264 R265 R266: "RES, 330, 5%, 0.1 W, 0603"
R219: "RES, 118k ohm, 0.1%, 0.125W, 0805"
R220: "RES, 5.62 k, 0.1%, 0.125 W, 0805"
R221: "RES, 249k ohm, 1%, 0.125W, 0805"
R222 R226 R231 R232 R233 R235 R236 R239 R240: "RES, 1.2 k, 5%, 0.1 W, 0603"
R223: "RES, 1.07 k, 0.1%, 0.125 W, 0805"
R224: "RES, 20.5 k, 1%, 0.125 W, 0805"
R225: "RES, 0.01, 1%, 0.25 W, 0805"
R244: "RES, 511, 1%, 0.1 W, 0603"
R246 R251: "RES, 10.0 k, 1%, 0.1 W, 0603"
R248 R255: "RES, 32.4 k, 0.1%, 0.1 W, 0603"
R253 R259: "RES, 25.5 k, 0.1%, 0.1 W, 0603"
R267 R270 R271 R277: "RES, 4.7 k, 5%, 0.063 W, 0402"
R268 R276: "RES, 0.1, 1%, 0.125 W, 0402"
R274: "RES, 100, 5%, 0.063 W, 0402"
S1: "Switch, Tactile, SPST-NO, 0.05A, 12V, SMD"
T1: "Transformer, 110 uH, SMT"
TP1 TP2 TP4 TP5 TP6 TP7 TP8 TP9 TP10 TP11 TP12 TP13 TP14 TP17: library part TP-040_RND, "Test Point 40mil pad 20mil drill"
TP3 TP16 TP26 TP27 TP28 TP29 TP32 TP35 TP36 TP37 TP38 TP39 TP40 TP41 TP42 TP43 TP44 TP45 TP46 TP47: "Test Point, Compact, SMT"
TP15 TP18 TP19 TP20 TP21 TP22 TP23 TP24 TP25 TP30 TP31 TP33 TP34 TP48 TP49 TP50 TP51: "Test Point, O.025\""
U1: "LOW-NOISE 1A TRANSFORMER DRIVERS FOR ISOLATED POWER SUPPLIES, DBV0006A"
U2 U7 U13: "36-V, 1-A, 4.17-µVRMS, RF LDO Voltage Regulator, RGW0020A"
U3: "3A SIMPLE SWITCHER® Power Module with 42V Maximum Input Voltage, 7-pin TO-PMOD, Pb-Free"
U4 U11: library part TPS70933DBVT, "IC REG LDO 1.2V 0.15A SOT23-5"
U5 U12: "High-Performance, 8000 VPK Reinforced Quad-Channel Digital Isolator, DW0016B"
U6 U8 U10: library part TPS70933DBVT, "IC REG LDO 1.8V 0.15A SOT23-5"
U9: "High-Performance, 8000 VPK Reinforced Quad Channel Digital Isolator, DW0016B"
U14: "Low-Noise, 900 kHz, RRIO, Precision Operational Amplifier, Zerø-Drift Series, 2.2 to 5.5 V, -40 to 125 degC, 5-pin SOT23 (DBV0005A), Green (RoHS & no Sb/Br)"
U15 U18 U20: "High-Bandwidth, High-Precision, Low THD+N, 16-Bit and 18-Bit Analog-to-Digital Converter (ADC) Drivers, DBV0006A"
U16: "SINGLE SCHMITT-TRIGGER BUFFER, DCK0005A"
U17 U27 U31: "Single 2-Input Positive-AND Gate, DCK0005A"
U19: "18-Bit, 2-MSPS, 20-mW, SAR ADC with Enhanced Serial Interface, RGE0024H"
U21 U28: "I2C BUS EEPROM (2-Wire), TSSOP-B8"
U22: "Low Noise, Very Low Drift, Precision Voltage Reference, -40 to 125 degC, 8-pin MSOP (DGK), Green (RoHS & no Sb/Br)"
U23: "Precision, Low Noise, Low Iq Operational Amplifier, 2.2 to 5.5 V, -40 to 125 degC, 5-pin SOT23 (DBV0005A), Green (RoHS & no Sb/Br)"
U24 U25: library part XC3S50AN-4TQ144C, "Spartan-3AN Non-Volatile FPGA, 108 User I/Os, 144-Pin TQFP, Standard Performance, Commercial Grade"
U26 U29 U30 U32: "Nanopower, 1.8V, Comparator with Voltage Reference, DCK0006A"
U33: "IC, Single Positive-Edge-Triggered D-Type Flip-Flop"
U34: library part REF6025AIDGK, "High-Precision Voltage Reference with Integrated High-Bandwidth Buffer, DGK0008A"
U35: "Low-Power Bidirectional I2C Isolators, D0008A"
U36: "Ultra-Low Jitter Programmable Oscillator with Internal EEPROM, SIA0008B"
U37: "500 Mbps High-Speed Differential Line Driver / Receivers with LVDS Input and LVTTL / LVCMOS Output, 1 Rx, -40 to +85 degC, 10-pin UQFN (RSE), Green (RoHS & no Sb/Br)"
Y1 Y2: library part AU-40.000MDE-T, "OSC, 125 MHz, 3.3V, SMD"
ZZ1: library part AssemblyNoteLabel
ZZ2 ZZ3 ZZ4: library part AssemblyNote

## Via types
v1: diameter 32, hole 16, Top Layer to Bottom Layer, tented both sides, 393 vias
v2: diameter 24, hole 12, Top Layer to Bottom Layer, tented both sides, 174 vias
v3: diameter 19.68, hole 7.87, Top Layer to Bottom Layer, tented both sides, 20 vias
v4: diameter 40, hole 20, Top Layer to Bottom Layer, tented both sides, 19 vias
v5: diameter 36, hole 16, Top Layer to Bottom Layer, tented both sides, 9 vias
v6: diameter 24, hole 12, Top Layer to Bottom Layer, 1 vias

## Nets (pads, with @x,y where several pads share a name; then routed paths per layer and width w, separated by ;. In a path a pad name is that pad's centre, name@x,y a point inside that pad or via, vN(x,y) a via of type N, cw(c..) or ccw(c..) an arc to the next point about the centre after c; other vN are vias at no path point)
1P2V: C15.1 C16.1 C166.1 C167.1 C168.1 C169.1 C170.1 C171.1 C172.1 C173.1 C174.1 C175.1 R237.2 TP4.1 TP46.1 U11.5 U25.22 U25.52 U25.94 U25.122 | length 1924
  Top Layer w20: TP4.1@6298.1,842.87 TP4.1@6310.93,830.04 ; v2(6987.58,2088.42) v2(6987.58,2088.42) C168.1@7027,2088.38 C174.1@7076,2088.38 7120.13,2088.38 C171.1@7127,2081.5 ; v2(7289,1819) 7291,1821 C173.1@7291,1857.38 7339,1857.38 C167.1@7340,1856.38 ; v2(7378,2533) 7378.62,2532.38 C169.1@7378.62,2504 C175.1@7378.62,2452 7378.62,2400.87 C170.1@7385.5,2394 ; C172.1@7651.62,2275 7651.62,2227 C166.1@7652.62,2226 7653.62,2227 v2(7701,2227)
  Bottom Layer w10: U25.122@6925.65,2088.42 v2(6987.58,2088.42) ; U25.94@7272.1,1761.65 7272.1,1800.57 7289,1817.46 v2(7289,1819) ; v2(7378,2533) 7389.46,2533 7409.9,2553.43 U25.22@7409.9,2592.35 ; v2(7701,2227) 7701.79,2226.21 U25.52@7756.35,2226.21
  Bottom Layer w20: TP4.1@6310.93,830.04 6479.96,830.04 6900,410 TP46.1@6900,177 R237.2@6726.73,177 ; R237.2@6725,178.73 R237.2@6726.73,177 ; R237.2@6727.87,175.87 R237.2@6726.73,177
  other v1: 6275.93,665.04 6265.93,715.04 6270.93,780.04
1P2V_ISO: C21.1 C22.1 C102.1 C103.1 C104.1 C105.1 C106.1 C107.1 C108.1 C109.1 C110.1 C111.1 R238.2 TP7.1 TP43.1 U4.5 U24.22 U24.52 U24.94 U24.122 | length 1817.8
  Top Layer w20: v1(2665,2200) 2707.38,2200 C109.1@2708.38,2199 C103.1@2708.38,2255 2708.38,2288.38 2720,2300 v2(2975,2300) 2978.46,2296.54 v1(2978.46,1933.46) ; C104.1@3061.62,2534.5 3061.62,2587.5 C110.1@3063.62,2589.5 v1(3063.62,2631.38) ; C107.1@3215,2331.5 3220.87,2325.62 C111.1@3278,2325.62 3279,2324.62 C105.1@3328,2324.62 3328.38,2325 v1(3370,2325)
  Bottom Layer w10: U24.122@2605.65,2198.42 2663.42,2198.42 v1(2665,2200) ; U24.94@2952.1,1871.65 2952.1,1910.57 2975,1933.46 v1(2978.46,1933.46) ; v1(3063.62,2631.38) 3089.9,2657.65 U24.22@3089.9,2702.35 ; v1(3370,2325) 3381.21,2336.21 U24.52@3436.35,2336.21
  Bottom Layer w15: TP43.1@2090,3330 2090,3440 2113.5,3463.5 R238.2@2215,3463.5
  Bottom Layer w20: TP7.1@1842.5,3295 2062.54,3295 TP43.1@2088.77,3321.23
  other v1: 1807.5,3355 1806.5,3407 1806.5,3455
1P8V: C176.1 C177.1 C178.1 C179.1 C184.1 C185.1 C188.1 C189.1 C190.1 C191.1 J17.2 R241.2 TP45.1 U25.119 U25.136 | length 3143.2
  Top Layer w20: C185.1@6865,2036.5 6871.81,2029.69 C176.1@6927.64,2029.69 ; C184.1@6875,2363.5 6882.87,2371.38 C178.1@6930,2371.38 ; C190.1@7120,2371.38 C191.1@7070,2371.38 C179.1@7020,2371.38 6988.62,2371.38 v2(6990,2372.76) 6931.38,2372.76 C178.1@6930,2371.38 ; C189.1@7125.5,2018.62 C188.1@7075.5,2018.62 C177.1@7025.5,2018.62 6994.38,2018.62 6983.32,2029.69 C176.1@6927.64,2029.69 ; C176.1@6927.64,2029.69 6927.64,2369.02 C178.1@6930,2371.38
  Bottom Layer w10: U25.119@6925.65,2029.36 6983.64,2029.36 v2(6993,2020) ; U25.136@6925.65,2364.01 6981.25,2364.01 v2(6990,2372.76)
  Bottom Layer w20: v1(5582,665) J17.2@6050,665 6320,935 6515,935 7117.97,332.03 R241.2@7204.29,332.03 7204.29,177.71 TP45.1@7205,177 TP45.1@7205,175
1P8V_1: C29.1 C30.1 J17.3 TP9.1 U6.5 | length 583.1
  Top Layer w30: TP9.1@5712.35,871.88 5876.12,871.88 5924,824 5924,622 5981,565 J17.3@6050,565
1P8V_ISO: C51.2 C59.1 C63.2 C134.1 C135.1 C136.1 C137.1 C142.1 C143.1 C146.1 C147.1 C148.1 C149.1 C192.2 J13.2 J24.3 R93.2 R242.2 TP47.1 U17.5 U19.16 U24.86 U24.95 U33.5 U37.5 | length 3310
  Top Layer w15: v1(1670.51,757.11) 1670.51,971.51 1765,1066 1765,1562 v1@1801,1598
  Top Layer w20: v1(1495.13,568.73) 1560.73,568.73 1670.51,678.51 v1(1670.51,757.11) ; C149.1@2917.62,2085 2919.62,2083 C148.1@2919.62,2028 2918.62,2027 C135.1@2918.62,1974 2918.62,1936.38 2909.69,1927.44 C134.1@2909.69,1880.36 2920,1870.05 2920,1827.92 C142.1@2920.56,1827.36 2920.56,1780.44 v1(2921,1780) ; C143.1@3106.5,1819 3113.38,1825.87 C136.1@3113.38,1872 3113.38,1926.62 v1(3109.58,1930.42) 3112.38,1933.21 C137.1@3112.38,1972.5 3112.38,2027.5 C146.1@3110.38,2029.5 3110.38,2078.5 C147.1@3109.38,2079.5
  Bottom Layer w8: v1(2920,1935) 2932.42,1922.58 U24.95@2932.42,1871.65
  Bottom Layer w10: U19.16@1664.84,2377.8 1664.84,2398.35 1692.75,2426.25 1715,2426.25 ; U24.86@3109.58,1871.65 v1(3109.58,1930.42)
  Bottom Layer w12: v1(2060,2090) 2050,2080 C59.1@2050,2038.62 2051.89,2040.51 U37.5@2094.21,2040.51
  Bottom Layer w15: U17.5@1613.72,713.52 1668.3,713.52 C51.2@1670.51,715.73 v1(1670.51,757.11) ; v1(1802,1598) 1885,1681 v1(1885,2025) C192.2@1931.38,2025 1934.1,2027.72 U33.5@1934.1,2091.4
  Bottom Layer w20: R242.2@1371,3095.5 v1(1432,3095.5) ; v1(1495.13,568.73) R93.2@1540.51,568.73 ; TP47.1@1615,2814 1615,3172 J13.2@1625,3182 ; 1715,2426.25 1735,2446.25 C63.2@1735,2477.69 1737.31,2480 v1(1745,2480)
1P8V_ISO1: C37.1 C38.1 J13.3 TP12.1 U10.5 | length 260.9
  Bottom Layer w30: TP12.1@1403,3183 1404,3182 J13.3@1525,3182 1525,3312 1531,3318
3P3V: C11.2 C25.2 C43.1 C86.1 C156.1 C157.1 C158.1 C159.1 C160.1 C161.1 C162.1 C163.1 C164.1 C165.1 C180.1 C181.1 C182.1 C183.1 C186.1 C187.1 C193.1 C194.1 C195.1 C196.1 C198.1 C199.1 C200.1 C201.1 C202.1 C203.1 C204.1 C205.1 C206.1 C207.1 C208.1 C209.1 C210.1 C211.1 C212.1 C213.1 C215.1 C216.1 C217.1 C218.1 C229.2 D22.2 D23.2 D24.2 D25.2 J19.6 R50.2 R61.1 R72.1 R74.2 R76.2 R179.2 R181.1 R182.1 R184.2 R188.1 R191.1 R196.1 R201.1 R202.1 R203.1 R205.2 R211.1 R214.1 R216.1 R218.1 R232.2 R235.2 R239.2 TP17.1 TP42.1 U5.1 U9.1 U12.16 U13.1 U13.3 U13.20 U25.14 U25.23 U25.36 U25.40 U25.61 U25.66 U25.86 U25.95 U25.108 U25.133 U35.1 Y2.4 | length 4538.1
  Top Layer w15: R211.1@5555,2416 5555,2371 v1(5556,2371)
  Top Layer w20: v1(5495,2210) 5496,2211 R203.1@5555,2211 ; v1(5500,2110) 5503,2113 R201.1@5555,2113 ; v1(5510,2314) R202.1@5555,2314 ; C161.1@6836,1765.5 6839.87,1761.62 C163.1@6887,1761.62 C162.1@6938,1761.62 6938.38,1762 v2(6970,1762) ; v2(6985,2304) 6985.38,2303.62 C164.1@7020,2303.62 C157.1@7070,2303.62 ; v1(7061.52,2521.52) R191.1@7061.52,2592.35 ; C212.1@7233.62,1955 C213.1@7233.62,1905 C201.1@7233.62,1855 v2(7233.62,1824.62) 7232.13,1823.13 C200.1@7232.13,1780 7240,1772.13 C207.1@7240,1730 ; C216.1@7255,2405 C215.1@7255,2455 C203.1@7255,2505 v2(7255,2533) 7251.35,2536.65 C202.1@7251.35,2587.35 7251.35,2634.48 C208.1@7259.23,2642.35 ; C206.1@7423.5,1720 7431.38,1727.87 C198.1@7431.38,1775 7431.38,1819.62 v2(7431,1820) 7431.38,1820.38 C199.1@7431.38,1850 C210.1@7431.38,1900 C211.1@7431.38,1950 ; C209.1@7438.5,2640 7446.38,2632.13 C204.1@7446.38,2585 7444,2582.62 v2(7444,2536) 7446.38,2533.62 C205.1@7446.38,2500 C217.1@7446.38,2450 C218.1@7446.38,2400 ; C193.1@7560,2463.62 C194.1@7610,2463.62 7645.19,2463.62 ; C195.1@7565,2051.38 C183.1@7615,2051.38 C196.1@7665,2051.38 7667.38,2049 v2(7702,2049) 7704.38,2051.38 C182.1@7740,2051.38 7759.12,2051.38 7767,2043.5 C187.1@7795,2043.5 ; C159.1@7615,1949.62 7616,1948.62 C158.1@7665,1948.62 7682,1965.62 v2(7682,1975) ; C181.1@7660,2463.62 7691.38,2463.62 7692.44,2464.69 C180.1@7737.64,2464.69 7784.76,2464.69 C186.1@7792.64,2472.56 ; C160.1@7743.5,2697 7751.38,2689.13 C165.1@7751.38,2643 7751.38,2593 C156.1@7750.38,2592 7750,2591.62 v1(7750,2560) ; v2(7872,1812) R196.1@7872,1866.5 ; 8026.5,2345.3 R216.1@8026.5,2303 R216.1@8034.5,2311 ; R214.1@8026.5,2367 v4(8081,2367) ; R181.1@8026.5,2557 v4(8081,2557) ; R182.1@8026.5,2621 v4(8081,2621) ; R218.1@8027.22,2430 v4(8081.72,2430)
  Bottom Layer w10: U25.133@6925.65,2304.95 6984.05,2304.95 v2(6985,2304) ; v2(7233.62,1824.62) 7252.42,1805.83 U25.95@7252.42,1761.65 ; U25.14@7252.42,2592.35 7252.42,2535.58 v2(7255,2533) ; U25.86@7429.58,1761.65 7429.58,1818.58 v2(7431,1820) ; U25.23@7429.58,2592.35 7429.58,2550.42 v2(7444,2536) ; v2(7682,1975) 7682,1972 7703.38,1950.62 U25.66@7756.35,1950.62 ; U25.36@7685.49,2592.35 7717.65,2592.35 v1(7750,2560) ; v2(7692,2463) 7755.79,2463 U25.40@7756.35,2462.43 ; v2(7702,2049) 7702.05,2049.05 U25.61@7756.35,2049.05
  Bottom Layer w12: v2(6970,1762) 6970.35,1761.65 U25.108@6996.51,1761.65
  Bottom Layer w15: U12.16@4571.01,2648 4647.62,2648 C43.1@4649,2649.38 4687.62,2649.38 v1(4686.24,2648)
  Bottom Layer w20: U35.1@4495.28,1118 C229.2@4566.38,1118 v1(4566.38,1161.62) ; U5.1@4568.02,1931.99 4644.63,1931.99 C11.2@4646.01,1930.61 v1(4681.01,1930.61) ; U9.1@4568.01,2460.98 4644.62,2460.98 C25.2@4646,2459.61 v1(4681,2459.61) ; v1(4646,2065.98) R72.1@4646,2112.36 ; v1(4646.01,1536.99) R61.1@4646.01,1583.37 ; R74.2@4649,2996.62 v1(4649,3048) ; v1(4693,1221) 4694,1220 R205.2@4694,1163 ; R50.2@4696,923 4696,872 v1(4697,871) ; v1(6508.87,68.37) R235.2@6508.87,120.87 ; R239.2@7115.78,492.54 7115.78,444.03 v1(7116.78,443.03) ; R232.2@7529,386.5 7529,306 v1(7530,305) TP42.1@7530,177 TP42.1@7530,170 ; v1(7955,2180) C86.1@8006.38,2180 8006.54,2179.84 Y2.4@8006.54,2118.31 ; R179.2@8155,2176.5 v1(8155,2220) ; R188.1@8179,1645 v1@8222.5,1645 ; R184.2@8181.5,1581 8225,1581 v1(8226,1580) ; D24.2@8851.5,738.5 v1(8900,738.5) ; D25.2@8851.5,880 v1(8895,880) ; D23.2@8851.5,1030 v1(8895,1030) ; D22.2@8851.5,1200 v1(8895,1200)
  other v1: 8223.5,1644 4925,2950 4995,2950 4995,3040 4995,3105
3P3V_ISO: C12.1 C26.1 C44.2 C50.2 C85.1 C92.1 C93.1 C94.1 C95.1 C96.1 C97.1 C98.1 C99.1 C100.1 C101.1 C116.1 C117.1 C118.1 C119.1 C122.1 C123.1 C129.1 C130.1 C131.1 C132.1 C138.1 C139.1 C140.1 C141.1 C144.1 C145.1 C151.1 C152.1 C153.1 C154.1 C230.1 C231.1 C232.1 C233.1 D9.2 D10.2 D11.2 D12.2 J14.6 J24.1 R62.2 R63.2 R73.2 R75.1 R87.2 R107.2 R119.2 R120.1 R121.1 R122.1 R153.1 R154.1 R155.1 R156.1 R157.1 R159.1 R161.2 R174.1 R176.1 R178.1 R204.2 R206.2 R231.2 R233.2 R236.2 R240.2 R243.2 R270.2 R271.2 R277.1 TP6.1 TP44.1 U5.16 U7.1 U7.3 U7.20 U9.16 U12.1 U16.5 U24.14 U24.23 U24.36 U24.40 U24.61 U24.66 U24.108 U24.133 U35.8 U36.1@2155,1257.17 U36.6@2155,1402.83 U37.10 Y1.4 | length 6253
  Top Layer w15: C97.1@2469.36,1823.56 2472.24,1820.68 C101.1@2529.36,1820.68 C95.1@2584.36,1820.68 v1(2617.98,1820.68)
  Top Layer w20: v1(2216,2825) 2218,2823 R159.1@2218,2873.5 ; v1(2307,2825) 2309,2823 R155.1@2309,2873.5 ; v1(2410,2825) 2412,2823 R157.1@2412,2873.5 ; v1(2495,2810) 2517,2832 R153.1@2517,2873.5 ; v1(2664.91,2415) 2710,2415 C94.1@2711,2416 C100.1@2711,2362 ; C145.1@2926.5,2765 2921.62,2760.13 C138.1@2921.62,2704.5 2921.62,2673.38 2934.62,2660.38 v1(2934.62,2634.62) C141.1@2934.62,2591.5 2934.62,2541.5 C151.1@2933.62,2540.5 2934.62,2539.5 C152.1@2934.62,2488.5 ; C144.1@3100.5,2748 3110.38,2738.13 C140.1@3110.38,2692 3115,2687.38 v1(3115,2630) 3115,2611.38 C139.1@3136.38,2590 3136.38,2538 C154.1@3134.38,2536 C153.1@3134.38,2487 ; C99.1@3327.62,2010 C93.1@3327.62,2061 3374,2061 v1(3374.38,2060.62) ; C132.1@3328.62,2111 C131.1@3328.62,2162 ; C117.1@3328.62,2213 C131.1@3328.62,2162 ; C130.1@3330.62,2468 3331.62,2469 C129.1@3331.62,2518 3332.62,2519 C119.1@3332.62,2571 3333.62,2570 v1(3380,2570) 3425.74,2570 3427.38,2571.64 C123.1@3427.38,2621.76 ; C116.1@3431.38,2163 3437.38,2163 3431.5,2168.87 C122.1@3431.5,2218 3431.38,2217.87 C116.1@3431.38,2165 3371,2165 v1(3368,2162) C131.1@3328.62,2162
  Bottom Layer w8: U37.10@2160.16,2039.51 U37.10@2165.08,2039.51 ; U37.10@2165.08,2040.51 2201.02,2040.51 C231.1@2209.65,2049.13 2228.27,2049.13 v1(2254.65,2075.51)
  Bottom Layer w10: U24.133@2605.65,2414.95 2664.95,2414.95 v1(2664.91,2415) ; v1@2607.98,1820.68 v1@2612.98,1815.68 ; v1(2617.98,1820.68) 2617.98,1841.65 2647.98,1871.65 U24.108@2676.51,1871.65 ; v1@2932.42,2636.83 U24.14@2932.42,2702.35 ; U24.23@3109.58,2702.35 3109.58,2635.42 v1(3115,2630) ; U24.36@3365.49,2702.35 3365.49,2764.51 ; v1(3368,2162) 3370.95,2159.05 U24.61@3436.35,2159.05 ; v1(3374.38,2060.62) U24.66@3436.35,2060.62 ; v1(3380,2570) 3382.43,2572.43 U24.40@3436.35,2572.43
  Bottom Layer w15: R87.2@1238.13,427.35 1238.13,466.73 v1(1250.13,478.73) ; U16.5@1624.42,452.64 1624.42,388.94 C50.2@1624.63,388.73 1624.63,342.24 v1(1626.13,340.73)
  Bottom Layer w20: R233.2@701.5,2939 749,2939 v1(750,2940) ; v1(1227,2869) 1227.5,2869.5 R240.2@1279,2869.5 ; v1(1880,1440) 1885,1435 R271.2@1885,1378.62 ; v1(1925,1115) R277.1@1981.38,1115 ; U36.1@2155,1257.17 2115,1217.17 C232.1@2115,1161.5 C233.1@2175,1161.5 v1(2175,1205) ; U36.6@2155,1402.83 2160,1407.83 v1(2160,1455) ; R270.2@2235,1373.62 v1(2235,1420) ; v1(2385,1850) 2383.62,1851.38 R161.2@2383.62,1895 2383.62,1913.16 2401.11,1930.65 Y1.4@2401.11,1961.2 2444.96,1961.2 C85.1@2462.65,1978.89 2499.02,1978.89 2525,2004.87 v1(2525,2005) ; v1(2495,2810) 2495,2845 2513.5,2863.5 R121.1@2564,2863.5 ; R236.2@2495,3436.5 2548.5,3436.5 v1(2550,3435) ; v1(2664.91,2415) 2725,2415 2775,2465 2858.12,2465 2932.42,2539.3 v1@2932.42,2636.83 ; v4(2747.07,3225) R243.2@2800.57,3225 ; R107.2@3066.5,3230 v4(3120,3230) ; v1(3156,3131) 3157,3132 D10.2@3157,3087.5 ; v1(3226,3130) 3227,3131 D9.2@3227,3086.5 ; v1(3300,3131) 3301,3132 D12.2@3301,3087.5 ; R119.2@3325.8,1547.5 3325.8,1499 v1(3326.3,1498.5) ; 3365.49,2764.51 3389.98,2789 C98.1@3435.38,2789 ; v1(3374,3133) 3375,3132 D11.2@3375,3087.5 ; R120.1@3390.8,1547.5 3390.8,1499 v1(3391.3,1498.5) ; C96.1@3433.5,2840 3435.38,2838.13 C98.1@3435.38,2789 ; v1(3435,2700) 3436.38,2701.38 C92.1@3436.38,2737 3435.38,2738 C98.1@3435.38,2789 ; TP6.1@3528,3519 3528,3370 3590,3308 3590,3160.5 R231.2@3592,3158.5 ; R122.1@3581.5,2040 v1(3636,2040) v1@3637,2041 ; R156.1@3618.2,2885.5 v1(3618.2,2931.5) ; R154.1@3680.2,2883.5 v1(3680.2,2929.5) ; R178.1@3814.2,2881.5 v4(3814.2,2945) ; R174.1@3878.2,2881.5 v4(3878.2,2945) ; TP44.1@3903,3197 TP44.1@3903,3165 ; v1(3905,3025) 3903,3027 TP44.1@3903,3165 ; v4(3940,2939.4) 3942.2,2937.2 R176.1@3942.2,2880.5 ; v1(4015,3165) TP44.1@3903,3165 ; v1(4071,2460.98) 4072.38,2459.61 C26.1@4111,2459.61 4112.38,2460.98 U9.16@4193.99,2460.98 ; v1(4071.01,1931.99) 4072.39,1930.61 C12.1@4111.01,1930.61 4112.39,1931.99 U5.16@4194,1931.99 ; v1(4082.62,2649.38) C44.2@4119,2649.38 4195.61,2649.38 U12.1@4196.99,2648 ; v1(4100,1225) 4101,1224 R204.2@4101,1166 ; v1(4101,864) R206.2@4101,926 ; v1(4111,2070.98) R73.2@4111,2112.36 ; v1(4111.01,1541.99) R62.2@4111.01,1583.37 ; R75.1@4119,2996.62 v1(4119,3038) ; v1(4221,1158.76) 4220.62,1158.38 C230.1@4220.62,1117 4221.62,1118 U35.8@4280.72,1118
  other v1: 3465,3500 3590,3500 3395,3560 3465,3560 3590,3560
5V_ISO: C49.2 C55.2 C77.2 C79.1 C88.2 C219.2 C228.2 D4.1 J12.2 R102.2 TP40.1 U14.5 U15.6 U18.6 U20.6 U22.2 U23.5 U34.1 U34.2 | length 1500.3
  Bottom Layer w10: U34.2@1536.59,1444.8 1550.15,1444.8
  Bottom Layer w15: C77.2@405,1631.52 407.91,1634.42 U23.5@470.87,1634.42 ; U22.2@1100.6,1372.8 1184.3,1372.8 C79.1@1192,1380.5 1239.5,1380.5 v1(1240,1380)
  Bottom Layer w20: C77.2@405,1631.52 v1(405,1683.02) ; v1(824.6,1907.6) 825.1,1907.09 872.6,1907.09 D4.1@872.69,1907 ; U14.5@868.4,1718.13 868.4,1785.91 C55.2@868.5,1786 868.5,1833.5 v1(869,1834) ; U18.6@1021.4,2240.13 1021.4,2263.4 1032,2274 1032,2304.5 C228.2@1033.5,2306 v1(1080,2306) ; U20.6@1021.4,2537.13 1021.4,2560.4 1032,2571 1032,2601.5 C219.2@1033.5,2603 v1(1080,2603) 1143,2540 v1(1498,2540) R102.2@1498,2488.62 ; v1(1116,1822) 1113,1819 C49.2@1113,1773.5 1116.09,1770.4 U15.6@1190.87,1770.4 ; TP40.1@1135,3009 1135,3185 J12.2@1137,3187 J12.2@1137,3210
  other v1: 1616,1410 1616,1465
5V_ISO1: J12.3 R52.2 TP1.1 U2.1 U2.3 U2.20 | length 416.5
  Bottom Layer w30: J12.3@1237,3187 1237,3254 1330,3347 TP1.1@1330,3565
5VDC: C13.1 C14.1 C27.1 C28.1 C45.1 C46.1 L1.1 L2.2 R222.2 R254.2 R255.2 T1.2 TP2.1 TP5.1 TP10.1 TP35.1 U1.2 U1.5 U6.1 U11.1 U13.13 U13.15 U13.16 | length 3368
  Top Layer w10: U13.13@5126.25,3271.3 v6(5126.25,3306.25)
  Top Layer w20: v1@6275.93,320.04 v1(6280.93,320.04) ; v1(6285.93,400.04) v1@6290.93,400.04 ; TP5.1@6325.93,225.04 6360.97,190 7755,190 v1(7865,300) 8240,675 L1.1@8240,925
  Top Layer w30: TP2.1@4996,3556 TP2.1@4999,3553
  Bottom Layer w15: v1(5014,3354) 5061.75,3306.25 v6(5126.25,3306.25)
  Bottom Layer w20: v1(4670.39,3499.61) 4670.39,3552.48 4673.43,3555.52 U1.2@4787.94,3555.52 U1.5@4896.21,3555.52 4994.04,3555.52 TP2.1@4996,3557.48 ; R254.2@5638,3114.62 v2(5638,3188) ; R255.2@5647,2728 v2(5686,2728)
  Bottom Layer w30: v1(4667,3620) 4670.39,3616.61 T1.2@4670.39,3552.48 ; TP2.1@4996,3557.48 R222.2@4996,3679.5 ; TP35.1@7864,177 7864,299 v1(7865,300)
  other v1: 5667.35,371.88 5672.35,451.88 4966.25,3391.3 5100,3540 5160,3540 5220,3540 5100,3610 5160,3610 5220,3610 5100,3680 5160,3680 5220,3680
+12VDC: C39.1 C40.1 D2.1 R219.2 R221.2 R226.2 TP16.1 U3.1 | length 1488.3
  Bottom Layer w20: R219.2@5859,3411 5859,3312 5899,3272 TP16.1@6026,3272 6027,3273 R221.2@6027,3486 ; D2.1@6673.5,3533.32 D2.1@6676.19,3536 ; 6716.59,3471.92 6818.5,3370 7135,3370 7276,3511 R226.2@7276,3838.5
+12VDC_IN: C8.1 D2.2 J5.2
A1P8V_ISO: C33.1 C34.1 R208.1 R234.2 TP11.1 TP41.1 U8.5 | length 2202
  Bottom Layer w15: TP11.1@558.5,3248 558.5,3150.99 R234.2@560,3149.5
  Bottom Layer w20: 195,3170.5 195,3140 250,3085 388,3085 789,2684 1552.19,2684 v1(1655,2581.19) 1658.62,2577.56 R208.1@1658.62,2531.19
  Bottom Layer w30: TP41.1@232,3241 551.5,3241 TP11.1@558.5,3248
ADC_CONVST: R45.2 U24.129 U33.1 | length 839.8
  Bottom Layer w8: R45.2@1858.62,2180 1860.22,2178.4 U33.1@1934.1,2178.4 1934.1,2224.1 1945,2235 2370,2235 2471.21,2336.21 U24.129@2605.65,2336.21
ADC_CONVST1: R207.2 U24.57 | length 596.3
  Bottom Layer w8: U24.57@3436.35,2237.79 3947.79,2237.79 3970,2260 R207.2@4023.5,2260
ADC_CONVST_FPGA: R260.1 U25.140 | length 2492
  Bottom Layer w8: R260.1@4711.5,2260 4711.5,2336.5 4940,2565 6205,2565 6272.7,2632.7 6470.05,2632.7 6660,2442.75 U25.140@6925.65,2442.75
ADC_CSN: U19.24 U24.130 | length 918.1
  Bottom Layer w8: U19.24@1729.8,2253.79 2343.79,2253.79 2445.9,2355.9 U24.130@2605.65,2355.9
ADC_MRESETN: U16.4 U17.1 U24.72 | length 3417.5
  Top Layer w10: v1(1717.82,503.82) 1801.65,420 3152,420 3513,781 v1(3513,1910)
  Bottom Layer w10: U17.1@1613.72,624.94 1613.72,596.14 1624.42,585.44 U16.4@1624.42,503.82 v1(1717.82,503.82) ; U24.72@3436.35,1942.51 3480.49,1942.51 v1(3513,1910)
ADC_RESETN: R244.2 U19.2 | length 1480.9
  Bottom Layer w10: R244.2@1564,865.5 1767,1068.5 1767,2121.42 1684.53,2203.89 U19.2@1684.53,2228.2
ADC_RVS: U19.21 U24.134 | length 926.3
  Bottom Layer w8: U19.21@1729.8,2312.84 2287.84,2312.84 2409.64,2434.64 U24.134@2605.65,2434.64
ADC_SCLK: U19.23 U24.131 | length 919.8
  Bottom Layer w8: U19.23@1730.98,2272.3 U19.23@1729.8,2273.47 2328.47,2273.47 2430.58,2375.58 U24.131@2605.65,2375.58
ADC_SDI: U19.22 U24.132 | length 918.1
  Bottom Layer w8: U19.22@1729.8,2293.16 2300,2293.16 2402.11,2395.27 U24.132@2605.65,2395.27
ADC_SDO0: U19.20 U24.135 | length 926.3
  Bottom Layer w8: U19.20@1729.8,2332.53 2283.53,2332.53 2405.32,2454.32 U24.135@2605.65,2454.32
